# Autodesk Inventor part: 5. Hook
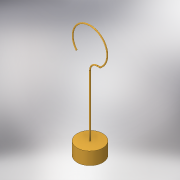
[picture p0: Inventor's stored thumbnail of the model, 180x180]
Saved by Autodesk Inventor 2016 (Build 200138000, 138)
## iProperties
Created: 2016-01
Part Number: 5. Hook
Material: Generic
Document SubType Name: Modeling
Designer: Black Falcon
Density: 1 g/cm^3
Appearance: Brass - Satin
Author: Black Falcon
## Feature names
1. Extrusion1
2. Sweep1
## Parameters: d0 = 25.4 mm, d1 = 12.7 mm, d2 = 0, d5 = 1.27 mm, d6 = 0, d7 = 0, d8 = 50.8 mm, d9 = 7.62 mm
